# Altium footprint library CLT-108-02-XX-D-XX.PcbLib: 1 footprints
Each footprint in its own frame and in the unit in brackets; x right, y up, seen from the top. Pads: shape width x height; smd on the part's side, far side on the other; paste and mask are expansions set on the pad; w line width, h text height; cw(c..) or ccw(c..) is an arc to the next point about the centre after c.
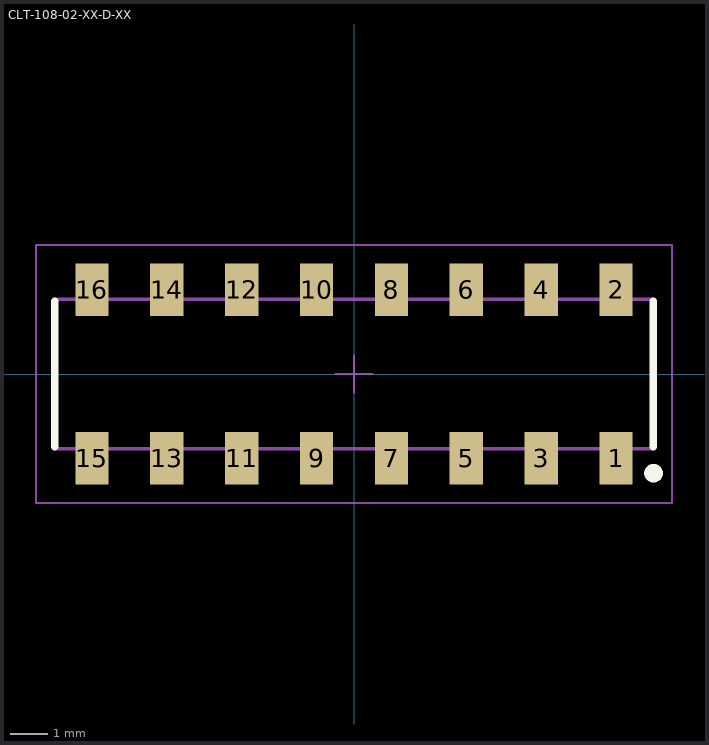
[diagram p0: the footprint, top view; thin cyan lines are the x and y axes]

## CLT-108-02-XX-D-XX [mm] "2.00mm pitch, 16 pin, header; low profile"
height 2.13
pads (16):
  rect 0.89x1.4 smd mask+0: 1(7,-2.25) 2(7,2.25) 3(5,-2.25) 4(5,2.25) 5(3,-2.25) 6(3,2.25) 7(1,-2.25) 8(1,2.25) 9(-1,-2.25) 10(-1,2.25) 11(-3,-2.25) 12(-3,2.25) 13(-5,-2.25) 14(-5,2.25) 15(-7,-2.25) 16(-7,2.25)
Top Overlay:
  circle w0.25: c8,-2.65 r0.125
  lines w0.2: -8,-1.95 -8,1.95 ; 8,-1.95 8,1.95
Mechanical 12:
  lines w0.001: -8,-2 -8,2 8,2 8,-2 -8,-2
Mechanical 13:
  lines w0.1: -8,-2 -8,2 8,2 8,-2 -8,-2
  text ".Designator" at 0.254,0.254 h1.52
Mechanical 15:
  lines w0.05: -0.5,0 0.5,0 ; 0,-0.5 0,0.5 ; -8.5,-3.45 -8.5,3.45 8.5,3.45 8.5,-3.45 -8.5,-3.45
